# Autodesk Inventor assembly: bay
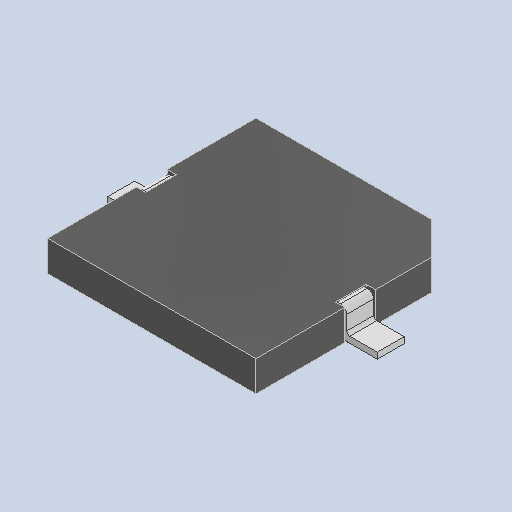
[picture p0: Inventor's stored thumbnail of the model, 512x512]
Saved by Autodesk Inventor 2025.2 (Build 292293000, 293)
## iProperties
Created: 2025-04
Part Number: bay
Description: PART--DESC
Document SubType Name: Assembly
Designer: BennF
Author: BennF
Revision Number: NONE
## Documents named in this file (3)
- C:\Users\BennF\Nextcloud\Benutzer\CNC JarBeRi\existing parts\Electronics\RepRap A4988 Shied (USE WITHOUT ARDUINO)\reprap-a4988-1.snapshot.1\RepRap\RepRap\bay_2.iam
- C:\Users\BennF\Nextcloud\Benutzer\CNC JarBeRi\existing parts\Electronics\RepRap A4988 Shied (USE WITHOUT ARDUINO)\reprap-a4988-1.snapshot.1\RepRap\RepRap\bay Geometry.ipt
- C:\Users\BennF\Nextcloud\Benutzer\CNC JarBeRi\existing parts\Electronics\RepRap A4988 Shied (USE WITHOUT ARDUINO)\reprap-a4988-1.snapshot.1\RepRap\RepRap\pin14.ipt
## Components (2 placed, 2 different names)
1. bay Geometry
2. pin14
